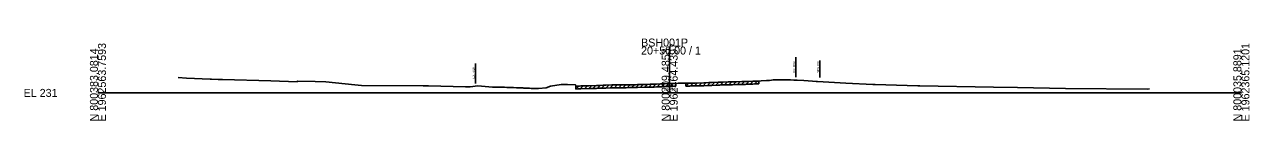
# Model space of a CAD drawing. Extents: x -26 to 1403, y -10 to 19587.
# Drawn here: x -25.7 to 402.8, y 4490.3 to 4519.1 of the extents above; entities that cross this region are included whole.
import ezdxf

# ---------------------------------------------------------------- set-up
doc = ezdxf.new("R2010")
doc.units = 0
for name, color, linetype in [('Default', 7, 'Continuous'), ('RD_GPK_XS_Cell', 7, 'Continuous'), ('RD_XS_ExGround', 7, 'Continuous'), ('RD_XS_ExPaveRet', 7, 'Continuous'), ('RD_XS_ExRW', 7, 'Continuous'), ('RD_XS_NewRW', 7, 'Continuous'), ('RD_XS_TX_Elev_EX', 7, 'Continuous')]:
    doc.layers.add(name, color=color, linetype=linetype)

msp = doc.modelspace()

# ---------------------------------------------------------------- linework, layer by layer
at = {"layer": 'RD_GPK_XS_Cell'}
for p, q in [((200, 4500), (200, 4516.24)), ((0, 4500), (200, 4500)), ((200, 4500), (400, 4500))]:
    msp.add_line(p, q, dxfattribs=at)
at = {"layer": 'RD_XS_ExGround'}
msp.add_lwpolyline([(28.05, 4505.41), (30.97, 4505.17), (39.26, 4504.83), (39.76, 4504.82), (42.05, 4504.73), (43.62, 4504.66), (60.48, 4504.2), (69.64, 4503.9), (69.79, 4504.14), (76, 4504.01), (79.73, 4503.82), (89.89, 4502.82), (92.25, 4502.63), (113.78, 4502.49), (114.47, 4502.46), (115.62, 4502.46), (128.55, 4502.12), (130.16, 4502.1), (132.88, 4502.42), (138.08, 4502.06), (141.37, 4502.04), (141.98, 4502), (142.28, 4501.99), (143.02, 4501.95), (143.46, 4501.93), (145.37, 4501.85), (146.37, 4501.81), (148.69, 4501.75), (149.03, 4501.71), (149.64, 4501.67), (150.94, 4501.6), (151.6, 4501.57), (154.09, 4501.53), (156.84, 4501.81), (158.26, 4502.36), (162.09, 4502.98), (164.23, 4502.89), (167.07, 4502.81), (167.17, 4502.36), (168.04, 4502.41), (168.42, 4502.41), (168.89, 4502.42), (171.68, 4502.5), (174.4, 4502.58), (175.23, 4502.61), (176.72, 4502.66), (177.29, 4502.68), (177.65, 4502.69), (179.72, 4502.77), (180.04, 4502.77), (180.39, 4502.77), (181.72, 4502.78), (182.55, 4502.78), (183.02, 4502.78), (184.81, 4502.81), (186.18, 4502.84), (186.69, 4502.85), (188.03, 4502.87), (188.78, 4502.89), (191.7, 4502.97), (192.28, 4502.99), (193.15, 4503.01), (194.53, 4503.06), (195.34, 4503.09), (196.82, 4503.14), (197.41, 4503.16), (198.2, 4503.19), (200.29, 4503.26), (201.12, 4503.3), (201.56, 4503.32), (202.15, 4503.35), (203, 4503.36), (206.58, 4503.41), (207.04, 4503.41), (207.83, 4503.42), (208.96, 4503.45), (211.91, 4503.53), (213.71, 4503.59), (214.73, 4503.63), (216.97, 4503.72), (217.6, 4503.75), (218.41, 4503.77), (220.46, 4503.82), (221.98, 4503.87), (223.34, 4503.9), (225.21, 4503.96), (226.49, 4504), (226.98, 4504.02), (229.1, 4504.1), (230.28, 4504.15), (231.17, 4504.12), (232.04, 4504.2), (233.84, 4504.31), (234.88, 4504.39), (235.58, 4504.44), (236.24, 4504.53), (237.74, 4504.56), (239.33, 4504.56), (240.63, 4504.54), (241.2, 4504.54), (242.22, 4504.53), (243.48, 4504.51), (244.55, 4504.47), (246.91, 4504.32), (249.93, 4504.1), (251.22, 4504.01), (251.72, 4503.98), (261.68, 4503.43), (271.11, 4502.92), (271.91, 4502.91), (286.84, 4502.44), (287.55, 4502.43), (313.24, 4501.96), (321.68, 4501.88), (338.46, 4501.58), (367.01, 4501.33), (367.8, 4501.37)], dxfattribs=at)
at = {"layer": 'RD_XS_ExPaveRet'}
for p, q in [((222.18, 4502.87), (223.21, 4503.9)), ((223.68, 4502.91), (224.71, 4503.94)), ((225.18, 4502.96), (226.21, 4503.99)), ((226.68, 4503), (227.72, 4504.04)), ((228.18, 4503.06), (229.22, 4504.1)), ((229.68, 4503.12), (230.69, 4504.13)), ((231.15, 4504.12), (231.15, 4503.12)), ((167.17, 4501.36), (168.22, 4502.41)), ((167.17, 4501.36), (167.17, 4502.36)), ((167.17, 4501.36), (168.04, 4501.41)), ((168.04, 4501.41), (168.42, 4501.41)), ((168.42, 4501.41), (168.89, 4501.42)), ((168.67, 4501.42), (169.7, 4502.44)), ((168.89, 4501.42), (171.68, 4501.5)), ((170.17, 4501.46), (171.2, 4502.48)), ((171.67, 4501.49), (172.7, 4502.53)), ((171.68, 4501.5), (174.4, 4501.58)), ((173.17, 4501.54), (174.2, 4502.58)), ((174.4, 4501.58), (175.23, 4501.61)), ((174.67, 4501.59), (175.71, 4502.63)), ((175.23, 4501.61), (176.72, 4501.66)), ((176.17, 4501.64), (177.21, 4502.68)), ((176.72, 4501.66), (177.29, 4501.68)), ((177.29, 4501.68), (177.65, 4501.69)), ((177.65, 4501.69), (179.72, 4501.77)), ((177.67, 4501.69), (178.71, 4502.73)), ((179.17, 4501.75), (180.19, 4502.77)), ((179.72, 4501.77), (180.04, 4501.77)), ((180.04, 4501.77), (180.39, 4501.77)), ((180.39, 4501.77), (181.72, 4501.78)), ((180.67, 4501.77), (181.67, 4502.77)), ((181.72, 4501.78), (182.55, 4501.78)), ((182.17, 4501.78), (183.18, 4502.79)), ((182.55, 4501.78), (183.02, 4501.78)), ((183.02, 4501.78), (184.81, 4501.81)), ((183.67, 4501.79), (184.69, 4502.81)), ((184.81, 4501.81), (186.18, 4501.84)), ((185.17, 4501.82), (186.19, 4502.84)), ((186.18, 4501.84), (186.69, 4501.85)), ((186.67, 4501.85), (187.69, 4502.87)), ((186.69, 4501.85), (188.03, 4501.87)), ((188.03, 4501.87), (188.78, 4501.89)), ((188.17, 4501.88), (189.2, 4502.9)), ((188.78, 4501.89), (191.7, 4501.97)), ((189.67, 4501.92), (190.7, 4502.94)), ((191.17, 4501.96), (192.2, 4502.98)), ((191.7, 4501.97), (192.28, 4501.99)), ((192.28, 4501.99), (193.15, 4502.01)), ((192.67, 4502), (193.7, 4503.03)), ((193.15, 4502.01), (194.53, 4502.06)), ((194.17, 4502.05), (195.21, 4503.08)), ((194.53, 4502.06), (195.34, 4502.09)), ((195.34, 4502.09), (196.82, 4502.14)), ((195.67, 4502.1), (196.71, 4503.13)), ((196.82, 4502.14), (197.41, 4502.16)), ((197.17, 4502.15), (198.21, 4503.19)), ((197.41, 4502.16), (198.2, 4502.19)), ((198.2, 4502.19), (200.29, 4502.26)), ((198.67, 4502.2), (199.71, 4503.24)), ((200.17, 4502.25), (201.22, 4503.31)), ((200.29, 4502.26), (201.12, 4502.3)), ((201.12, 4502.3), (201.56, 4502.32)), ((201.56, 4502.32), (202.13, 4502.35)), ((202.13, 4503.35), (202.13, 4502.35)), ((205.68, 4502.4), (206.69, 4503.41)), ((205.68, 4502.4), (205.68, 4503.4)), ((205.68, 4502.4), (206.58, 4502.41)), ((206.58, 4502.41), (207.04, 4502.41)), ((207.04, 4502.41), (207.83, 4502.42)), ((207.18, 4502.41), (208.2, 4503.43)), ((207.83, 4502.42), (208.96, 4502.45)), ((208.68, 4502.44), (209.7, 4503.47)), ((208.96, 4502.45), (211.91, 4502.53)), ((210.18, 4502.48), (211.2, 4503.51)), ((211.68, 4502.52), (212.71, 4503.55)), ((211.91, 4502.53), (213.71, 4502.59)), ((213.18, 4502.57), (214.22, 4503.61)), ((213.71, 4502.59), (214.73, 4502.63)), ((214.68, 4502.63), (215.72, 4503.67)), ((214.73, 4502.63), (216.97, 4502.72)), ((216.18, 4502.69), (217.22, 4503.73)), ((216.97, 4502.72), (217.6, 4502.75)), ((217.6, 4502.75), (218.41, 4502.77)), ((217.68, 4502.75), (218.7, 4503.78)), ((218.41, 4502.77), (220.46, 4502.82)), ((219.18, 4502.79), (220.21, 4503.82)), ((220.46, 4502.82), (221.98, 4502.87)), ((220.68, 4502.83), (221.7, 4503.86)), ((221.98, 4502.87), (223.34, 4502.9)), ((223.34, 4502.9), (225.21, 4502.96)), ((225.21, 4502.96), (226.49, 4503)), ((226.49, 4503), (226.98, 4503.02)), ((226.98, 4503.02), (229.1, 4503.1)), ((229.1, 4503.1), (230.28, 4503.15)), ((230.28, 4503.15), (231.15, 4503.12))]:
    msp.add_line(p, q, dxfattribs=at)
at = {"layer": 'RD_XS_ExRW'}
for p, q in [((244.16, 4505.48), (244.16, 4512.48)), ((132.06, 4503.32), (132.06, 4510.32))]:
    msp.add_line(p, q, dxfattribs=at)
at = {"layer": 'RD_XS_NewRW'}
msp.add_line((252.49, 4511.4), (252.49, 4505.4), dxfattribs=at)

# ---------------------------------------------------------------- texts
at = {"layer": 'Default'}
msp.add_text('-', height=0.0001, dxfattribs=at).set_placement((0, 4500))
at = {"layer": 'RD_GPK_XS_Cell'}
for s, p in [('E 1962563.7593', (2.8, 4490)), ('E 1962464.4397', (202.8, 4490)), ('E 1962365.1201', (402.8, 4490)), ('N 800383.0814', (0, 4490)), ('N 800209.4853', (200, 4490)), ('N 800035.8891', (400, 4490))]:
    msp.add_text(s, height=2.8, rotation=90, dxfattribs=at).set_placement(p)
for s, p in [('BSH001P', (190, 4516.24)), ('20+50.00 / 1', (190, 4513.44)), ('EL 231', (-26, 4498.6))]:
    msp.add_text(s, height=2.8, dxfattribs=at).set_placement(p)
at = {"layer": 'RD_XS_ExRW'}
for p in [(131.81, 4505), (243.91, 4507.16)]:
    msp.add_text('EX. R/W ', height=0.75, rotation=90, dxfattribs=at).set_placement(p)
at = {"layer": 'RD_XS_NewRW'}
msp.add_text('NEW R/W ', height=0.65, rotation=90, dxfattribs=at).set_placement((252.22, 4506.96))
at = {"layer": 'RD_XS_TX_Elev_EX'}
msp.add_text('234.25', height=1, dxfattribs=at).set_placement((197.95, 4500.75))

doc.saveas('drawing.dxf')
